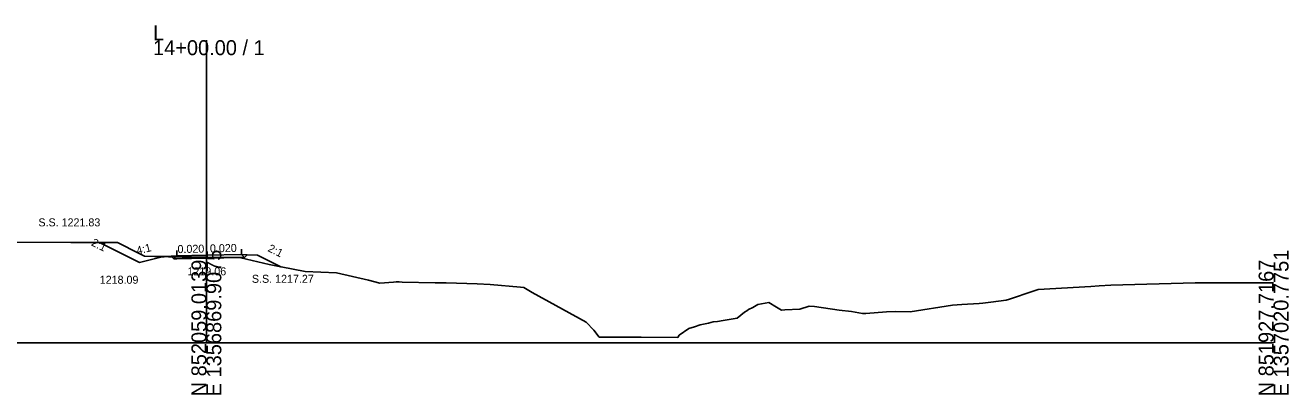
# Model space of a CAD drawing. Extents: x -26 to 3203, y -10 to 4066.
# Drawn here: x 166.1 to 402.8, y 3490.3 to 3559.5 of the extents above; entities that cross this region are included whole.
import ezdxf

# ---------------------------------------------------------------- set-up
doc = ezdxf.new("R2010")
doc.units = 0
for name, color, linetype in [('Exist Cross Section Cell', 7, 'Continuous'), ('Exist XS Center Line Elevation Label', 7, 'Continuous'), ('Exist XS Ground Line', 7, 'Continuous'), ('Prop XS Ditch Slope Text', 7, 'Continuous'), ('Prop XS Ditch Standard Text', 7, 'Continuous'), ('Prop XS Dump Level', 7, 'Continuous'), ('Prop XS Earthwork Shape', 7, 'Continuous'), ('Prop XS EOT Tick Mark', 7, 'Continuous'), ('Prop XS Finish Grade', 7, 'Continuous'), ('Prop XS Finish Grade Earthwork', 7, 'Continuous'), ('Prop XS Finish Grade Pavement', 7, 'Continuous'), ('Prop XS Pvmt Edge Slope', 7, 'Continuous'), ('Prop XS SE Text', 7, 'Continuous'), ('Prop XS Side Slope Text', 7, 'Continuous'), ('Prop XS SS Elevation Text', 7, 'Continuous'), ('Prop XS Subgrade Earthwork', 7, 'Continuous')]:
    doc.layers.add(name, color=color, linetype=linetype)

msp = doc.modelspace()

# ---------------------------------------------------------------- linework, layer by layer
at = {"layer": 'Exist Cross Section Cell'}
for p, q in [((200, 3500), (200, 3556.71)), ((0, 3500), (200, 3500)), ((200, 3500), (400, 3500))]:
    msp.add_line(p, q, dxfattribs=at)
at = {"layer": 'Exist XS Ground Line'}
for p, q in [((163.5, 3518.87), (174.59, 3518.84)), ((174.59, 3518.84), (183.37, 3518.82)), ((183.37, 3518.82), (187.4, 3516.78)), ((187.4, 3516.78), (188.4, 3516.26)), ((188.4, 3516.26), (190.27, 3516.21)), ((190.27, 3516.21), (195.47, 3516.1)), ((195.47, 3516.1), (200, 3516.06)), ((200, 3516.06), (201.41, 3516.04)), ((201.41, 3516.04), (206.43, 3515.97)), ((206.43, 3515.97), (211.78, 3514.71)), ((211.78, 3514.71), (218.51, 3513.37)), ((218.51, 3513.37), (221.44, 3513.28)), ((221.44, 3513.28), (224.41, 3513.15)), ((224.41, 3513.15), (230.37, 3511.74)), ((230.37, 3511.74), (232.5, 3511.2)), ((232.5, 3511.2), (235.05, 3511.41)), ((235.05, 3511.41), (235.57, 3511.44)), ((235.57, 3511.44), (236.13, 3511.43)), ((236.13, 3511.43), (236.68, 3511.41)), ((236.68, 3511.41), (242.87, 3511.27)), ((242.87, 3511.27), (244.95, 3511.26)), ((244.95, 3511.26), (250.74, 3511.05)), ((250.74, 3511.05), (253.18, 3510.93)), ((253.18, 3510.93), (258.86, 3510.45)), ((258.86, 3510.45), (259.52, 3510.41)), ((259.52, 3510.41), (261.07, 3509.47)), ((261.07, 3509.47), (271.17, 3503.9)), ((350.53, 3508.23), (354.92, 3509.69)), ((354.92, 3509.69), (355.87, 3510.03)), ((355.87, 3510.03), (365.74, 3510.57)), ((365.74, 3510.57), (367.3, 3510.7)), ((367.3, 3510.7), (369.48, 3510.82)), ((369.48, 3510.82), (385.31, 3511.27)), ((385.31, 3511.27), (389.87, 3511.27)), ((389.87, 3511.27), (400, 3511.27)), ((302.38, 3506.67), (303.32, 3507.2)), ((303.32, 3507.2), (305.38, 3507.58)), ((305.38, 3507.58), (306.82, 3506.73)), ((311.19, 3506.36), (312.98, 3506.9)), ((312.98, 3506.9), (313.97, 3506.85)), ((313.97, 3506.85), (318.58, 3506.12)), ((331.89, 3505.84), (339.84, 3507.07)), ((339.84, 3507.07), (341.56, 3507.21)), ((341.56, 3507.21), (344.83, 3507.39)), ((344.83, 3507.39), (345.51, 3507.47)), ((345.51, 3507.47), (347.01, 3507.66)), ((347.01, 3507.66), (349.91, 3508.02)), ((349.91, 3508.02), (350.53, 3508.23)), ((296.82, 3504.2), (299.46, 3504.65)), ((299.46, 3504.65), (300.83, 3505.8)), ((300.83, 3505.8), (301.26, 3506.03)), ((301.26, 3506.03), (301.6, 3506.24)), ((301.6, 3506.24), (302.38, 3506.67)), ((306.82, 3506.73), (307.78, 3506.15)), ((307.78, 3506.15), (308.39, 3506.19)), ((308.39, 3506.19), (311.19, 3506.36)), ((318.58, 3506.12), (320.88, 3505.9)), ((320.88, 3505.9), (322.99, 3505.55)), ((322.99, 3505.55), (323.59, 3505.52)), ((323.59, 3505.52), (327.45, 3505.86)), ((327.45, 3505.86), (329.12, 3505.88)), ((329.12, 3505.88), (331.89, 3505.84)), ((271.17, 3503.9), (272.59, 3502.38)), ((272.59, 3502.38), (273.62, 3501.08)), ((288.59, 3501.44), (290.39, 3502.73)), ((290.39, 3502.73), (291.47, 3503.03)), ((291.47, 3503.03), (292.52, 3503.37)), ((292.52, 3503.37), (294.13, 3503.68)), ((294.13, 3503.68), (294.98, 3503.95)), ((294.98, 3503.95), (295.76, 3504.02)), ((295.76, 3504.02), (296.82, 3504.2)), ((273.62, 3501.08), (274.37, 3501.08)), ((274.37, 3501.08), (281.49, 3501.08)), ((281.49, 3501.08), (288.34, 3501.05)), ((288.34, 3501.05), (288.59, 3501.44))]:
    msp.add_line(p, q, dxfattribs=at)
at = {"layer": 'Prop XS Dump Level'}
for p, q in [((194.45, 3516.33), (200, 3516.44)), ((200, 3516.44), (206.6, 3516.57))]:
    msp.add_line(p, q, dxfattribs=at)
at = {"layer": 'Prop XS Earthwork Shape'}
for points in [[(183.37, 3518.82), (187.4, 3516.78), (188.4, 3516.26), (190.27, 3516.21), (192.4, 3516.17), (191.45, 3516.09), (187.45, 3515.09), (179.98, 3518.83)], [(193.53, 3516.14), (193.42, 3516.25), (192.4, 3516.17)], [(204.79, 3516), (206.43, 3515.97), (211.78, 3514.71), (213.96, 3514.27), (209.6, 3516.45), (207.62, 3516.53), (207.13, 3516.04), (206.6, 3516.03)], [(195.47, 3516.1), (200, 3516.06), (201.41, 3516.04), (204.79, 3516), (200, 3515.9), (194.45, 3515.79), (193.89, 3515.78), (193.53, 3516.14)]]:
    msp.add_lwpolyline(points, close=True, dxfattribs=at)
at = {"layer": 'Prop XS EOT Tick Mark'}
for p, q in [((194.45, 3516.33), (194.45, 3517.33)), ((206.6, 3516.57), (206.6, 3517.57))]:
    msp.add_line(p, q, dxfattribs=at)
at = {"layer": 'Prop XS Finish Grade'}
for p, q in [((194.45, 3516.33), (193.42, 3516.25)), ((206.6, 3516.57), (207.62, 3516.53))]:
    msp.add_line(p, q, dxfattribs=at)
at = {"layer": 'Prop XS Finish Grade Earthwork'}
for p, q in [((187.45, 3515.09), (179.98, 3518.83)), ((193.42, 3516.25), (191.45, 3516.09)), ((207.62, 3516.53), (209.6, 3516.45)), ((209.6, 3516.45), (213.96, 3514.27)), ((191.45, 3516.09), (187.45, 3515.09))]:
    msp.add_line(p, q, dxfattribs=at)
at = {"layer": 'Prop XS Finish Grade Pavement'}
for p, q in [((194.45, 3516.33), (200, 3516.44)), ((200, 3516.44), (206.6, 3516.57))]:
    msp.add_line(p, q, dxfattribs=at)
at = {"layer": 'Prop XS Pvmt Edge Slope'}
for p, q in [((194.45, 3516.33), (193.89, 3515.78)), ((206.6, 3516.57), (207.13, 3516.04))]:
    msp.add_line(p, q, dxfattribs=at)
at = {"layer": 'Prop XS Subgrade Earthwork'}
for p, q in [((193.89, 3515.78), (193.42, 3516.25)), ((207.13, 3516.04), (207.62, 3516.53)), ((194.45, 3515.79), (193.89, 3515.78)), ((200, 3515.9), (194.45, 3515.79)), ((206.6, 3516.03), (200, 3515.9)), ((206.6, 3516.03), (207.13, 3516.04))]:
    msp.add_line(p, q, dxfattribs=at)

# ---------------------------------------------------------------- texts
at = {"layer": 'Exist Cross Section Cell'}
for s, p in [('L', (190, 3556.71)), ('14+00.00 / 1', (190, 3553.91))]:
    msp.add_text(s, height=2.8, dxfattribs=at).set_placement(p)
for s, p in [('E 1356869.9075', (202.8, 3490)), ('E 1357020.7751', (402.8, 3490)), ('N 852059.0139', (200, 3490)), ('N 851927.7167', (400, 3490))]:
    msp.add_text(s, height=2.8, rotation=90, dxfattribs=at).set_placement(p)
at = {"layer": 'Exist XS Center Line Elevation Label'}
msp.add_text('1219.06', height=1.5, dxfattribs=at).set_placement((196.46, 3512.67))
at = {"layer": 'Prop XS Ditch Slope Text'}
msp.add_text('4:1', height=1.5, rotation=14.0362, dxfattribs=at).set_placement((187.08, 3516.55))
at = {"layer": 'Prop XS Ditch Standard Text'}
msp.add_text('1218.09', height=1.5, dxfattribs=at).set_placement((180.01, 3511.09))
at = {"layer": 'Prop XS Dump Level'}
for p in [(209.6, 3516.41), (191.45, 3516.05)]:
    msp.add_text('Case1', height=0.04, dxfattribs=at).set_placement(p)
at = {"layer": 'Prop XS SE Text'}
for p in [(194.6, 3516.83), (200.68, 3516.96)]:
    msp.add_text('0.020', height=1.5, rotation=1.1458, dxfattribs=at).set_placement(p)
at = {"layer": 'Prop XS Side Slope Text'}
for p in [(178.3, 3518.34), (211.39, 3517.24)]:
    msp.add_text('2:1', height=1.5, rotation=333.4349, dxfattribs=at).set_placement(p)
at = {"layer": 'Prop XS SS Elevation Text'}
for s, p in [('S.S. 1221.83', (168.52, 3521.84)), ('S.S. 1217.27', (208.53, 3511.27))]:
    msp.add_text(s, height=1.5, dxfattribs=at).set_placement(p)

doc.saveas('drawing.dxf')
